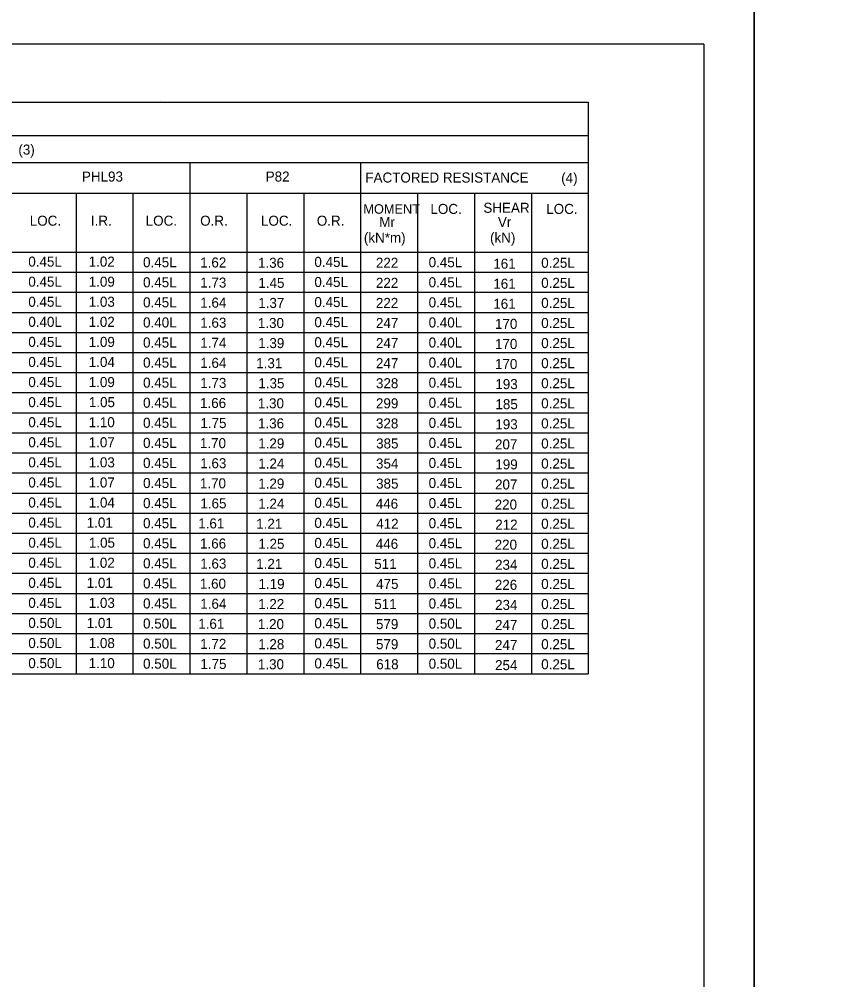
# Model space of a CAD drawing. Extents: x -5022 to -159, y 1126 to 7226.
# Drawn here: x -4059.9 to -3813, y 5583.2 to 5870.3 of the extents above; entities that cross this region are included whole.
import ezdxf

# ---------------------------------------------------------------- set-up
doc = ezdxf.new("R2010")
doc.units = 0
for name, color, linetype in [('2', 7, 'Continuous'), ('3', 7, 'Continuous'), ('PLT-BNDY', 7, 'Continuous')]:
    doc.layers.add(name, color=color, linetype=linetype)

msp = doc.modelspace()

# ---------------------------------------------------------------- linework, layer by layer
at = {"layer": '2'}
for q in [(-4641.13, 5862.81), (-3855.13, 5298.81)]:
    msp.add_line((-3855.13, 5862.81), q, dxfattribs=at)
at = {"layer": '3'}
for p, q in [((-4017.59, 5845.98), (-4017.59, 5845.98)), ((-4603.47, 5845.48), (-3889.73, 5845.48)), ((-3889.73, 5845.48), (-3889.73, 5674.68)), ((-4603.47, 5835.56), (-3889.73, 5835.56)), ((-4603.47, 5827.49), (-3889.73, 5827.49)), ((-4008.88, 5827.5), (-4008.88, 5674.68)), ((-3957.81, 5827.5), (-3957.81, 5674.68)), ((-4264.2, 5818.29), (-3889.73, 5818.29)), ((-4042.92, 5818.29), (-4042.92, 5674.68)), ((-4042.92, 5818.29), (-4042.92, 5674.68)), ((-4025.9, 5818.29), (-4025.9, 5674.68)), ((-3991.86, 5818.29), (-3991.86, 5674.68)), ((-3974.84, 5818.29), (-3974.84, 5674.68)), ((-3940.79, 5818.29), (-3940.79, 5674.68)), ((-3923.77, 5818.29), (-3923.77, 5674.68)), ((-3906.75, 5818.29), (-3906.75, 5674.68)), ((-4603.47, 5800.68), (-3889.73, 5800.68)), ((-4586, 5794.68), (-3889.73, 5794.68)), ((-4586, 5788.68), (-3889.73, 5788.68)), ((-4603.47, 5782.68), (-3889.73, 5782.68)), ((-4586, 5776.68), (-3889.73, 5776.68)), ((-4586, 5770.68), (-3889.73, 5770.68)), ((-4603.47, 5764.68), (-3889.73, 5764.68)), ((-4586, 5758.68), (-3889.73, 5758.68)), ((-4586, 5752.68), (-3889.73, 5752.68)), ((-4603.47, 5746.68), (-3889.73, 5746.68)), ((-4586, 5740.68), (-3889.73, 5740.68)), ((-4586, 5734.68), (-3889.73, 5734.68)), ((-4603.47, 5728.68), (-3889.73, 5728.68)), ((-4586, 5722.68), (-3889.73, 5722.68)), ((-4586, 5716.68), (-3889.73, 5716.68)), ((-4603.47, 5710.68), (-3889.73, 5710.68)), ((-4586, 5704.68), (-3889.73, 5704.68)), ((-4586, 5698.68), (-3889.73, 5698.68)), ((-4603.47, 5692.68), (-3889.73, 5692.68)), ((-4586, 5686.68), (-3889.73, 5686.68)), ((-4586, 5680.68), (-3889.73, 5680.68)), ((-4603.47, 5674.68), (-3889.73, 5674.68))]:
    msp.add_line(p, q, dxfattribs=at)
at = {"layer": 'PLT-BNDY'}
for points in [[(-4681.13, 5877.81), (-3840.13, 5877.81), (-3840.13, 5283.81), (-4681.13, 5283.81)], [(-3840.13, 5877.81), (-2999.13, 5877.81), (-2999.13, 5283.81), (-3840.13, 5283.81)]]:
    msp.add_lwpolyline(points, close=True, dxfattribs=at)

# ---------------------------------------------------------------- texts
at = {"layer": '2'}
for s, height, p in [('(3)', 3, (-4060.18, 5829.84)), ('PHL93', 3, (-4041.17, 5821.78)), ('P82', 3, (-3986.21, 5821.78)), ('FACTORED RESISTANCE', 3.0001, (-3956.4, 5821.48)), ('(4)', 3, (-3897.83, 5821.38)), ('MOMENT', 2.85, (-3957, 5812.16)), ('LOC.', 3, (-3936.94, 5812.1)), ('SHEAR', 3, (-3921.1, 5812.44)), ('LOC.', 3, (-3902.3, 5812.1)), ('LOC.', 3, (-4056.77, 5808.58)), ('I.R.', 3, (-4038.49, 5808.58)), ('LOC.', 3, (-4022.1, 5808.58)), ('O.R.', 3, (-4005.81, 5808.58)), ('LOC.', 3, (-3987.62, 5808.58)), ('O.R.', 3, (-3970.92, 5808.58)), ('Mr', 3, (-3952.25, 5808.17)), ('Vr', 3, (-3916.76, 5808.17)), ('(kN*m)', 3, (-3956.85, 5803.52)), ('(kN)', 3, (-3919.11, 5803.52)), ('0.45L', 3, (-4057.21, 5796.35)), ('1.02', 3, (-4039.16, 5796.35)), ('0.45L', 3, (-4022.89, 5796.17)), ('1.62', 3, (-4005.8, 5796.09)), ('1.36', 3, (-3988.51, 5796)), ('0.45L', 3, (-3971.65, 5796.26)), ('222', 3, (-3953.25, 5796)), ('0.45L', 3, (-3937.48, 5796.17)), ('161', 3, (-3918.14, 5795.74)), ('0.25L', 3, (-3903.81, 5796)), ('0.45L', 3, (-4057.21, 5790.35)), ('1.09', 3, (-4039.14, 5790.35)), ('0.45L', 3, (-4022.89, 5790.17)), ('1.73', 3, (-4005.78, 5790.09)), ('1.45', 3, (-3988.41, 5790)), ('0.45L', 3, (-3971.65, 5790.26)), ('222', 3, (-3953.25, 5790)), ('0.45L', 3, (-3937.48, 5790.17)), ('161', 3, (-3918.14, 5789.74)), ('0.25L', 3, (-3903.81, 5790)), ('0.45L', 3, (-4057.21, 5784.35)), ('1.03', 3, (-4039.14, 5784.35)), ('0.45L', 3, (-4022.89, 5784.17)), ('1.64', 3, (-4005.78, 5784.09)), ('1.37', 3, (-3988.45, 5784)), ('0.45L', 3, (-3971.65, 5784.26)), ('222', 3, (-3953.25, 5784)), ('0.45L', 3, (-3937.48, 5784.17)), ('161', 3, (-3918.14, 5783.74)), ('0.25L', 3, (-3903.81, 5784)), ('0.40L', 3, (-4057.21, 5778.35)), ('1.02', 3, (-4039.16, 5778.35)), ('0.40L', 3, (-4022.89, 5778.17)), ('1.63', 3, (-4005.78, 5778.09)), ('1.30', 3, (-3988.55, 5778)), ('0.45L', 3, (-3971.65, 5778.26)), ('247', 3, (-3953.24, 5778)), ('0.40L', 3, (-3937.48, 5778.17)), ('170', 3, (-3917.64, 5777.74)), ('0.25L', 3, (-3903.81, 5778)), ('0.45L', 3, (-4057.21, 5772.35)), ('1.09', 3, (-4039.14, 5772.35)), ('0.45L', 3, (-4022.89, 5772.17)), ('1.74', 3, (-4005.78, 5772.09)), ('1.39', 3, (-3988.45, 5772)), ('0.45L', 3, (-3971.65, 5772.26)), ('247', 3, (-3953.24, 5772)), ('0.40L', 3, (-3937.48, 5772.17)), ('170', 3, (-3917.64, 5771.74)), ('0.25L', 3, (-3903.81, 5772)), ('0.45L', 3, (-4057.21, 5766.35)), ('1.04', 3, (-4039.13, 5766.35)), ('0.45L', 3, (-4022.89, 5766.17)), ('1.64', 3, (-4005.78, 5766.09)), ('1.31', 3, (-3989.05, 5766)), ('0.45L', 3, (-3971.65, 5766.26)), ('247', 3, (-3953.24, 5766)), ('0.40L', 3, (-3937.48, 5766.17)), ('170', 3, (-3917.64, 5765.74)), ('0.25L', 3, (-3903.81, 5766)), ('0.45L', 3, (-4057.21, 5760.35)), ('1.09', 3, (-4039.14, 5760.35)), ('0.45L', 3, (-4022.89, 5760.17)), ('1.73', 3, (-4005.78, 5760.09)), ('1.35', 3, (-3988.41, 5760)), ('0.45L', 3, (-3971.65, 5760.26)), ('328', 3, (-3953.23, 5760)), ('0.45L', 3, (-3937.48, 5760.17)), ('193', 3, (-3917.53, 5759.74)), ('0.25L', 3, (-3903.81, 5760)), ('0.45L', 3, (-4057.21, 5754.35)), ('1.05', 3, (-4039.1, 5754.35)), ('0.45L', 3, (-4022.89, 5754.17)), ('1.66', 3, (-4005.85, 5754.09)), ('1.30', 3, (-3988.55, 5754)), ('0.45L', 3, (-3971.65, 5754.26)), ('299', 3, (-3953.23, 5754)), ('0.45L', 3, (-3937.48, 5754.17)), ('0.25L', 3, (-3903.81, 5754)), ('185', 3, (-3917.5, 5753.74)), ('0.45L', 3, (-4057.21, 5748.35)), ('1.10', 3, (-4039.16, 5748.35)), ('0.45L', 3, (-4022.89, 5748.17)), ('1.75', 3, (-4005.75, 5748.09)), ('0.45L', 3, (-3971.65, 5748.26)), ('0.45L', 3, (-3937.48, 5748.17)), ('1.36', 3, (-3988.51, 5748)), ('328', 3, (-3953.23, 5748)), ('193', 3, (-3917.53, 5747.74)), ('0.25L', 3, (-3903.81, 5748)), ('0.45L', 3, (-4057.21, 5742.35)), ('1.07', 3, (-4039.15, 5742.35)), ('0.45L', 3, (-4022.89, 5742.17)), ('1.70', 3, (-4005.89, 5742.09)), ('1.29', 3, (-3988.45, 5742)), ('0.45L', 3, (-3971.65, 5742.26)), ('385', 3, (-3953.19, 5742)), ('0.45L', 3, (-3937.48, 5742.17)), ('207', 3, (-3917.63, 5741.74)), ('0.25L', 3, (-3903.81, 5742)), ('0.45L', 3, (-4057.21, 5736.35)), ('1.03', 3, (-4039.14, 5736.35)), ('0.45L', 3, (-4022.89, 5736.17)), ('1.63', 3, (-4005.78, 5736.09)), ('1.24', 3, (-3988.44, 5736)), ('0.45L', 3, (-3971.65, 5736.26)), ('354', 3, (-3953.22, 5736)), ('0.45L', 3, (-3937.48, 5736.17)), ('199', 3, (-3917.54, 5735.74)), ('0.25L', 3, (-3903.81, 5736)), ('0.45L', 3, (-4057.21, 5730.34)), ('1.07', 3, (-4039.15, 5730.34)), ('0.45L', 3, (-4022.89, 5730.17)), ('1.70', 3, (-4005.89, 5730.08)), ('1.29', 3, (-3988.45, 5730)), ('0.45L', 3, (-3971.65, 5730.26)), ('385', 3, (-3953.19, 5730)), ('0.45L', 3, (-3937.48, 5730.17)), ('207', 3, (-3917.63, 5729.74)), ('0.25L', 3, (-3903.81, 5730)), ('0.45L', 3, (-4057.21, 5724.34)), ('1.04', 3, (-4039.13, 5724.34)), ('0.45L', 3, (-4022.89, 5724.17)), ('1.65', 3, (-4005.75, 5724.08)), ('1.24', 3, (-3988.44, 5724)), ('0.45L', 3, (-3971.65, 5724.26)), ('446', 3, (-3953.29, 5724)), ('0.45L', 3, (-3937.48, 5724.17)), ('220', 3, (-3917.73, 5723.74)), ('0.25L', 3, (-3903.81, 5724)), ('0.45L', 3, (-4057.21, 5718.34)), ('1.01', 3, (-4039.74, 5718.34)), ('0.45L', 3, (-4022.89, 5718.17)), ('1.61', 3, (-4006.39, 5718.09)), ('1.21', 3, (-3989.05, 5718)), ('0.45L', 3, (-3971.65, 5718.26)), ('412', 3, (-3953.16, 5718)), ('0.45L', 3, (-3937.48, 5718.17)), ('212', 3, (-3917.56, 5717.74)), ('0.25L', 3, (-3903.81, 5718)), ('0.45L', 3, (-4057.21, 5712.34)), ('1.05', 3, (-4039.1, 5712.34)), ('0.45L', 3, (-4022.89, 5712.17)), ('1.66', 3, (-4005.85, 5712.09)), ('1.25', 3, (-3988.41, 5712)), ('0.45L', 3, (-3971.65, 5712.26)), ('446', 3, (-3953.29, 5712)), ('0.45L', 3, (-3937.48, 5712.17)), ('220', 3, (-3917.73, 5711.74)), ('0.25L', 3, (-3903.81, 5712)), ('0.45L', 3, (-4057.21, 5706.34)), ('1.02', 3, (-4039.16, 5706.34)), ('0.45L', 3, (-4022.89, 5706.17)), ('1.63', 3, (-4005.78, 5706.09)), ('1.21', 3, (-3989.05, 5706)), ('0.45L', 3, (-3971.65, 5706.25)), ('511', 3, (-3953.75, 5706)), ('0.45L', 3, (-3937.48, 5706.17)), ('234', 3, (-3917.61, 5705.74)), ('0.25L', 3, (-3903.81, 5706)), ('0.45L', 3, (-4057.21, 5700.34)), ('1.01', 3, (-4039.74, 5700.34)), ('0.45L', 3, (-4022.89, 5700.17)), ('1.60', 3, (-4005.89, 5700.08)), ('1.19', 3, (-3988.37, 5700)), ('0.45L', 3, (-3971.65, 5700.26)), ('475', 3, (-3953.19, 5700)), ('0.45L', 3, (-3937.48, 5700.17)), ('226', 3, (-3917.68, 5699.74)), ('0.25L', 3, (-3903.81, 5700)), ('0.45L', 3, (-4057.21, 5694.35)), ('1.03', 3, (-4039.14, 5694.35)), ('0.45L', 3, (-4022.89, 5694.17)), ('1.64', 3, (-4005.78, 5694.08)), ('1.22', 3, (-3988.46, 5694)), ('0.45L', 3, (-3971.65, 5694.26)), ('511', 3, (-3953.75, 5694)), ('0.45L', 3, (-3937.48, 5694.17)), ('234', 3, (-3917.61, 5693.74)), ('0.25L', 3, (-3903.81, 5694)), ('0.50L', 3, (-4057.21, 5688.35)), ('1.01', 3, (-4039.74, 5688.35)), ('0.50L', 3, (-4022.89, 5688.17)), ('1.61', 3, (-4006.39, 5688.09)), ('1.20', 3, (-3988.55, 5688)), ('0.45L', 3, (-3971.65, 5688.26)), ('579', 3, (-3953.23, 5688)), ('0.50L', 3, (-3937.48, 5688.17)), ('247', 3, (-3917.63, 5687.74)), ('0.25L', 3, (-3903.81, 5688)), ('0.50L', 3, (-4057.21, 5682.34)), ('1.08', 3, (-4039.14, 5682.34)), ('0.50L', 3, (-4022.89, 5682.17)), ('1.72', 3, (-4005.8, 5682.09)), ('1.28', 3, (-3988.45, 5682)), ('0.45L', 3, (-3971.65, 5682.26)), ('579', 3, (-3953.23, 5682)), ('0.50L', 3, (-3937.48, 5682.17)), ('0.25L', 3, (-3903.81, 5682)), ('247', 3, (-3917.63, 5681.74)), ('0.50L', 3, (-4057.21, 5676.34)), ('1.10', 3, (-4039.16, 5676.34)), ('0.45L', 3, (-3971.65, 5676.26)), ('0.50L', 3, (-4022.89, 5676.17)), ('1.75', 3, (-4005.75, 5676.08)), ('1.30', 3, (-3988.55, 5676)), ('618', 3, (-3953.15, 5676)), ('0.50L', 3, (-3937.48, 5676.17)), ('254', 3, (-3917.61, 5675.74)), ('0.25L', 3, (-3903.81, 5676))]:
    msp.add_text(s, height=height, dxfattribs=at).set_placement(p)

doc.saveas('drawing.dxf')
